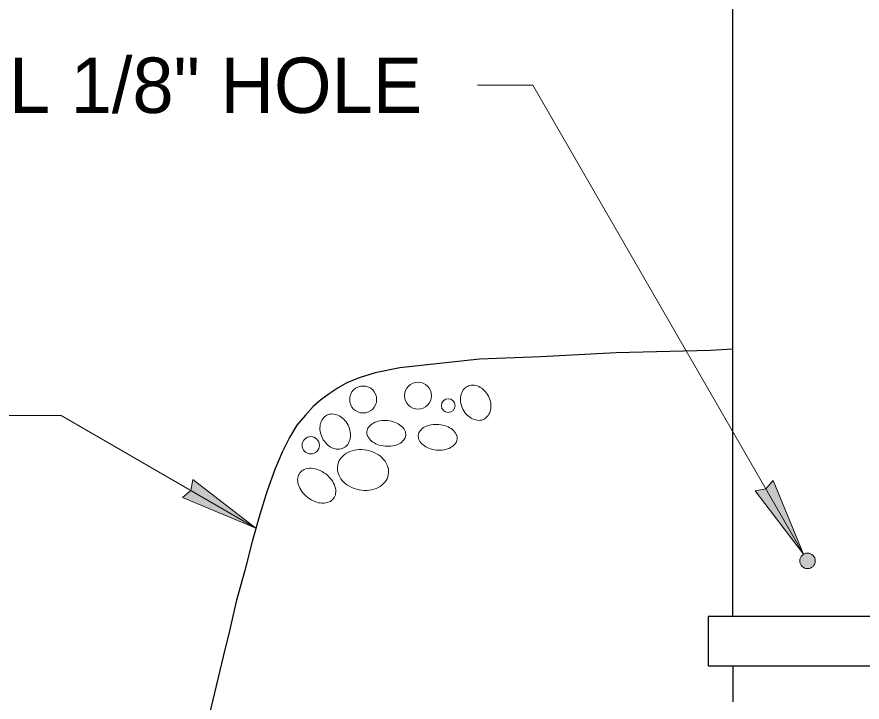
# Model space of a CAD drawing. Extents: x 99860 to 103153, y 99998 to 102077.
# Drawn here: x 100386.3 to 100630.4, y 100412.2 to 100610.1 of the extents above; entities that cross this region are included whole.
import ezdxf
from ezdxf.enums import TextEntityAlignment as Align

# ---------------------------------------------------------------- set-up
doc = ezdxf.new("R2010")
doc.units = 0
doc.header["$LTSCALE"] = 6.4
for name, color, linetype, lineweight in [('10', 7, 'Continuous', 13), ('11', 7, 'Continuous', 13), ('15', 7, 'Continuous', 13), ('20', 7, 'Continuous', 13), ('6', 7, 'Continuous', 25), ('7', 7, 'Continuous', 25)]:
    doc.layers.add(name, color=color, linetype=linetype, lineweight=lineweight)

msp = doc.modelspace()

# ---------------------------------------------------------------- hatches: boundary and pattern name
at = {"layer": '11'}
msp.add_hatch(color=256, dxfattribs=at).paths.add_polyline_path([(100616.908, 100452.959, 1), (100612.424, 100452.959, 1)])
at = {"layer": '15'}
for points in [[(100455.338, 100462.425), (100434.075, 100471.255), (100436.482, 100473.312), (100437.06, 100476.425)], [(100613.545, 100454.901), (100604.715, 100476.164), (100602.658, 100473.757), (100599.545, 100473.179)]]:
    msp.add_hatch(color=256, dxfattribs=at).paths.add_polyline_path(points)

# ---------------------------------------------------------------- linework, layer by layer
at = {"layer": '10'}
for centre, radius in [((100502.155, 100500.672), 3.892), ((100486.297, 100499.582), 3.892), ((100510.867, 100497.82), 1.968), ((100471.174, 100486.35), 2.498)]:
    msp.add_circle(centre, radius, dxfattribs=at)
for centre, radius, start, end in [((100517.882, 100500.463), 3.263, 88.95321, 116.92034), ((100517.861, 100499.346), 4.38, 64.87819, 88.95321), ((100518.796, 100499.82), 4.38, 144.88748, 168.96249), ((100517.882, 100500.463), 3.263, 116.92034, 144.88747), ((100517.418, 100498.4), 5.424, 44.82747, 64.87819), ((100516.452, 100497.44), 6.787, 26.92034, 44.82747), ((100519.821, 100499.62), 5.424, 168.96249, 189.01321), ((100521.166, 100499.834), 6.787, 189.01321, 206.92034), ((100516.452, 100497.44), 6.787, 9.01321, 26.92034), ((100521.166, 100499.834), 6.787, 206.92034, 224.82747), ((100518.822, 100497.453), 4.38, 324.88748, 348.96249), ((100517.797, 100497.653), 5.424, 348.96249, 9.01321), ((100478.217, 100491.493), 4.38, 144.88748, 168.96249), ((100477.302, 100492.136), 3.263, 116.92034, 144.88747), ((100477.302, 100492.136), 3.263, 88.95321, 116.92034), ((100477.282, 100491.018), 4.38, 64.87819, 88.95321), ((100476.839, 100490.073), 5.424, 44.82747, 64.87819), ((100475.873, 100489.113), 6.787, 26.92034, 44.82747), ((100520.2, 100498.873), 5.424, 224.82747, 244.87819), ((100519.757, 100497.928), 4.38, 244.87819, 268.95321), ((100519.737, 100496.811), 3.263, 268.95321, 296.92034), ((100519.737, 100496.811), 3.263, 296.92034, 324.88747), ((100479.242, 100491.293), 5.424, 168.96249, 189.01321), ((100475.873, 100489.113), 6.787, 9.01321, 26.92034), ((100489.855, 100490.091), 2.497, 142.14169, 174.34175), ((100491.261, 100488.998), 4.277, 117.67701, 142.14169), ((100492.098, 100487.402), 6.08, 99.58221, 117.67701), ((100492.509, 100484.967), 8.549, 84.34175, 99.58221), ((100492.509, 100484.967), 8.549, 69.10129, 84.34175), ((100493.39, 100487.274), 6.08, 51.00649, 69.10129), ((100494.524, 100488.675), 4.277, 26.54181, 51.00649), ((100506.104, 100487.889), 4.277, 117.67701, 142.14169), ((100506.941, 100486.292), 6.08, 99.58221, 117.67701), ((100507.352, 100483.857), 8.549, 84.34175, 99.58221), ((100507.352, 100483.857), 8.549, 69.10129, 84.34175), ((100508.233, 100486.164), 6.08, 51.00649, 69.10129), ((100480.587, 100491.507), 6.787, 189.01321, 206.92034), ((100477.218, 100489.326), 5.424, 348.96249, 9.01321), ((100489.855, 100490.091), 2.497, 174.34175, 206.54181), ((100491.448, 100490.886), 4.277, 206.54181, 231.00649), ((100496.117, 100489.47), 2.497, 322.14169, 354.34175), ((100496.117, 100489.47), 2.497, 354.34175, 26.54181), ((100504.698, 100488.981), 2.497, 174.34175, 206.54181), ((100504.698, 100488.981), 2.497, 142.14169, 174.34175), ((100509.367, 100487.565), 4.277, 26.54181, 51.00649), ((100510.96, 100488.361), 2.497, 354.34175, 26.54181), ((100480.587, 100491.507), 6.787, 206.92034, 224.82747), ((100479.621, 100490.546), 5.424, 224.82747, 244.87819), ((100479.157, 100488.483), 3.263, 296.92034, 324.88747), ((100478.243, 100489.126), 4.38, 324.88748, 348.96249), ((100492.582, 100492.287), 6.08, 231.00649, 249.10129), ((100493.463, 100494.595), 8.549, 249.10129, 264.34175), ((100493.874, 100492.159), 6.08, 279.58221, 297.67701), ((100494.711, 100490.563), 4.277, 297.67701, 322.14169), ((100506.291, 100489.777), 4.277, 206.54181, 231.00649), ((100507.425, 100491.178), 6.08, 231.00649, 249.10129), ((100509.554, 100489.454), 4.277, 297.67701, 322.14169), ((100510.96, 100488.361), 2.497, 322.14169, 354.34175), ((100479.178, 100489.601), 4.38, 244.87819, 268.95321), ((100479.157, 100488.483), 3.263, 268.95321, 296.92034), ((100484.68, 100478.795), 6.167, 116.93797, 140.98821), ((100485.328, 100477.518), 7.599, 96.821, 116.93797), ((100485.55, 100475.667), 9.463, 78.81267, 96.821), ((100485.55, 100475.667), 9.463, 60.80434, 78.81267), ((100493.463, 100494.595), 8.549, 264.34175, 279.58221), ((100508.306, 100493.485), 8.549, 249.10129, 264.34175), ((100508.306, 100493.485), 8.549, 264.34175, 279.58221), ((100508.717, 100491.05), 6.08, 279.58221, 297.67701), ((100483.486, 100479.762), 4.631, 140.98821, 168.81267), ((100486.459, 100477.295), 7.599, 40.68736, 60.80434), ((100487.545, 100478.228), 6.167, 16.63713, 40.68736), ((100470.427, 100476.551), 3.038, 111.92563, 142.60018), ((100471.07, 100474.954), 4.76, 87.52761, 111.92563), ((100470.997, 100473.261), 6.454, 68.73292, 87.52761), ((100470.168, 100471.132), 8.739, 52.60018, 68.73292), ((100483.486, 100479.762), 4.631, 168.81267, 196.63713), ((100489.017, 100478.668), 4.631, 348.81267, 16.63713), ((100472.137, 100476.35), 4.76, 173.27472, 197.67274), ((100470.427, 100476.551), 3.038, 142.60018, 173.27472), ((100470.168, 100471.132), 8.739, 36.46743, 52.60018), ((100484.958, 100480.202), 6.167, 196.63713, 220.68736), ((100489.017, 100478.668), 4.631, 320.98821, 348.81267), ((100473.752, 100476.864), 6.454, 197.67274, 216.46743), ((100472.006, 100472.49), 6.454, 17.67274, 36.46743), ((100473.62, 100473.004), 4.76, 353.27472, 17.67274), ((100486.044, 100481.135), 7.599, 220.68736, 240.80434), ((100486.953, 100482.763), 9.463, 240.80434, 258.81267), ((100487.823, 100479.635), 6.167, 296.93797, 320.98821), ((100475.589, 100478.222), 8.739, 216.46743, 232.60018), ((100475.33, 100472.802), 3.038, 322.60017, 353.27472), ((100486.953, 100482.763), 9.463, 258.81267, 276.821), ((100487.175, 100480.912), 7.599, 276.821, 296.93797), ((100475.589, 100478.222), 8.739, 232.60018, 248.73292), ((100474.76, 100476.093), 6.454, 248.73292, 267.52761), ((100474.687, 100474.4), 4.76, 267.52761, 291.92563), ((100475.33, 100472.802), 3.038, 291.92563, 322.60017)]:
    msp.add_arc(centre, radius, start, end, dxfattribs=at)
at = {"layer": '11'}
msp.add_circle((100614.666, 100452.959), 2.242, dxfattribs=at)
at = {"layer": '15'}
for p, q in [((100519.342, 100590.353), (100535.342, 100590.353)), ((100613.545, 100454.901), (100535.342, 100590.353)), ((100383.046, 100494.925), (100399.046, 100494.925)), ((100455.338, 100462.425), (100399.046, 100494.925))]:
    msp.add_line(p, q, dxfattribs=at)
for points in [[(100455.338, 100462.425), (100434.075, 100471.255), (100436.482, 100473.312), (100437.06, 100476.425)], [(100613.545, 100454.901), (100604.715, 100476.164), (100602.658, 100473.757), (100599.545, 100473.179)]]:
    msp.add_lwpolyline(points, close=True, dxfattribs=at)
at = {"layer": '6'}
for p, q in [((100593.126, 100436.937), (100593.126, 100828.687)), ((100593.126, 100422.612), (100593.126, 100412.212))]:
    msp.add_line(p, q, dxfattribs=at)
msp.add_lwpolyline([(100585.926, 100422.612), (100643.338, 100422.612), (100643.338, 100436.937), (100585.926, 100436.937)], close=True, dxfattribs=at)
at = {"layer": '7'}
msp.add_lwpolyline([(100593.126, 100514.087), (100586.626, 100513.712), (100559.376, 100513.05), (100537.513, 100511.912), (100519.926, 100511.187), (100506.638, 100509.787), (100496.938, 100508.712), (100489.776, 100507.262), (100485.138, 100505.812), (100481.563, 100504.425), (100479.038, 100502.975), (100476.513, 100501.175), (100474.013, 100499.375), (100471.876, 100497.6), (100469.688, 100495.075), (100467.163, 100492.2), (100465.051, 100488.637), (100462.901, 100484.337), (100460.751, 100479.325), (100458.576, 100473.187), (100456.426, 100466.337), (100454.251, 100458.512), (100452.138, 100450.2), (100449.638, 100441.262), (100447.488, 100431.887), (100446.315, 100427.396), (100445.349, 100423.29), (100442.862, 100412.865), (100441.23, 100406.135)], dxfattribs=at)

# ---------------------------------------------------------------- texts
at = {"layer": '20'}
msp.add_text('DRILL 1/8" HOLE', height=16, dxfattribs=at).set_placement((100503.344, 100582.353), align=Align.RIGHT)

doc.saveas('drawing.dxf')
